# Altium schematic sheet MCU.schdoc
size 297 x 209 mm; Symbol: Drawing-Symbol_A4; @Project Name: Pedal Steel; @Page Count: 1; @Update Date: 2026-10-20; @Create Date: 2026-10-20; @Schematic Name: Schematic1; @Page No: 1; @Page Name: P1; Company: EasyEDA.com; Version: V1.0; Page Size: A4; Device: Drawing-Symbol_A4; @Create Time: 17:29:51; @Update Time: 17:29:51; Border: 1; Width: 1170; Height: 825; Region Start: 1; X Region Count: 6; Y Region Count: 4; Blade Width: 10; Title Block Position: 3
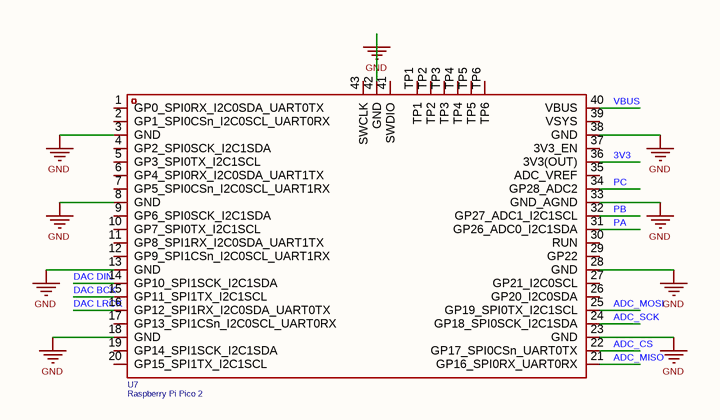
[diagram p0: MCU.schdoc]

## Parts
U7  Raspberry Pi Pico 2  [COMM-SMD_L51.0-W21.0-P2.54_SC0916]

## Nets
GND: U7.3(GND) U7.8(GND) U7.13(GND) U7.18(GND) U7.23(GND) U7.28(GND) U7.33(GND_AGND) U7.38(GND) U7.42(GND)
3V3: U7.36(3V3(OUT))
ADC_CS: U7.22(GP17_SPI0CSn_UART0TX)
ADC_MISO: U7.21(GP16_SPI0RX_UART0RX)
ADC_MOSI: U7.25(GP19_SPI0TX_I2C1SCL)
ADC_SCK: U7.24(GP18_SPI0SCK_I2C1SDA)
DAC BCK: U7.15(GP11_SPI1TX_I2C1SCL)
DAC DIN: U7.14(GP10_SPI1SCK_I2C1SDA)
DAC LRCK: U7.16(GP12_SPI1RX_I2C0SDA_UART0TX)
PA: U7.31(GP26_ADC0_I2C1SDA)
PB: U7.32(GP27_ADC1_I2C1SCL)
PC: U7.34(GP28_ADC2)
VBUS: U7.40(VBUS)

Not connected (* = marked no-connect by the designer): U7 1(GP0_SPI0RX_I2C0SDA_UART0TX) 2(GP1_SPI0CSn_I2C0SCL_UART0RX) 4(GP2_SPI0SCK_I2C1SDA) 5(GP3_SPI0TX_I2C1SCL) 6(GP4_SPI0RX_I2C0SDA_UART1TX) 7(GP5_SPI0CSn_I2C0SCL_UART1RX) 9(GP6_SPI0SCK_I2C1SDA) 10(GP7_SPI0TX_I2C1SCL) 11(GP8_SPI1RX_I2C0SDA_UART1TX) 12(GP9_SPI1CSn_I2C0SCL_UART1RX) 17(GP13_SPI1CSn_I2C0SCL_UART0RX) 19(GP14_SPI1SCK_I2C1SDA) 20(GP15_SPI1TX_I2C1SCL) 26(GP20_I2C0SDA) 27(GP21_I2C0SCL) 29(GP22) 30(RUN) 35(ADC_VREF) 37(3V3_EN) 39(VSYS) 41(SWDIO) 43(SWCLK) TP1 TP2 TP3 TP4 TP5 TP6

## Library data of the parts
U7 = Raspberry Pi Pico 2: Manufacturer: Raspberry Pi(树莓派); Symbol: PICO 2; AddInBom: yes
